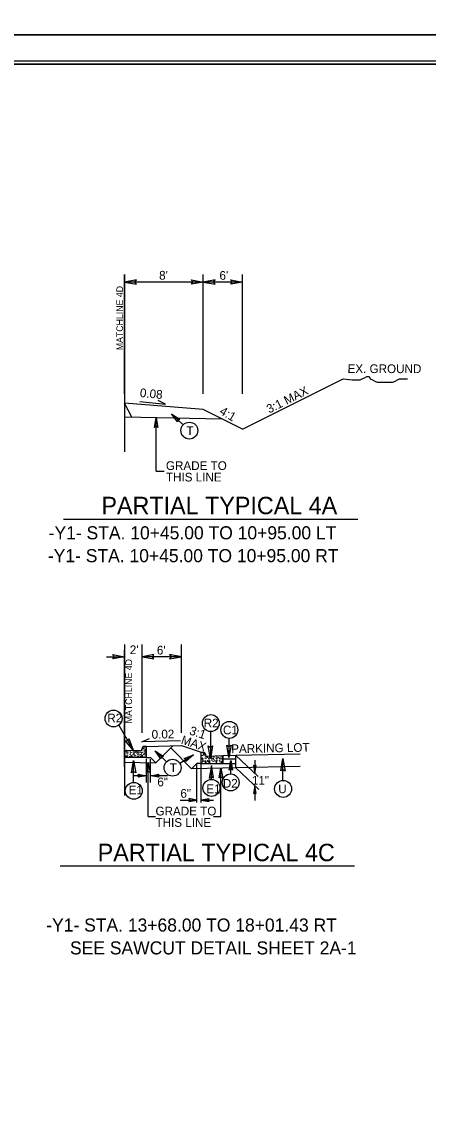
# Model space of a CAD drawing. Extents: x 2320980 to 2456309, y 595047 to 606177.
# Drawn here: x 2455879.6 to 2455941.7, y 596577.9 to 596743.6 of the extents above; entities that cross this region are included whole.
import ezdxf

# ---------------------------------------------------------------- set-up
doc = ezdxf.new("R2010")
doc.units = 0
for name, color, linetype in [('Matchline', 7, 'Continuous'), ('Matchline Text', 7, 'Continuous'), ('Old_Level_1', 7, 'Continuous'), ('Old_Level_2', 7, 'Continuous'), ('Old_Level_20', 7, 'Continuous'), ('Old_Level_21', 7, 'Continuous'), ('Old_Level_3', 7, 'Continuous'), ('Prop Dimension', 7, 'Continuous'), ('Prop Dimension Text', 7, 'Continuous'), ('Prop Terminator CELL', 7, 'Continuous'), ('Sheet Plan CELL', 7, 'Continuous'), ('Sheet Plot Border Inside CELL', 7, 'Continuous'), ('Sheet Plot Border Outside CELL', 7, 'Continuous'), ('Typical Berm CELL', 7, 'Continuous'), ('Typical Curb CELL', 7, 'Continuous'), ('Typical ID Circle CELL', 7, 'Continuous'), ('Typical Pavement Slope CELL', 7, 'Continuous'), ('Typical Pavement Slope Information CELL', 7, 'Continuous'), ('Typical Slope Point Local CELL', 7, 'Continuous'), ('Typical Terminator CELL', 7, 'Continuous')]:
    doc.layers.add(name, color=color, linetype=linetype)

msp = doc.modelspace()

# ---------------------------------------------------------------- linework, layer by layer
at = {"layer": 'Matchline'}
for p, q in [((2455895.35, 596705.01), (2455895.35, 596677.92)), ((2455895.35, 596648.55), (2455895.35, 596625.48))]:
    msp.add_line(p, q, dxfattribs=at)
at = {"layer": 'Old_Level_1'}
for p, q in [((2455922.11, 596631.78), (2455912.33, 596631.58)), ((2455922.11, 596629.91), (2455912.33, 596629.7))]:
    msp.add_line(p, q, dxfattribs=at)
at = {"layer": 'Old_Level_21'}
for p, q in [((2455895.35, 596686.78), (2455895.35, 596705.01)), ((2455907.35, 596703.85), (2455895.35, 596703.85)), ((2455907.35, 596686.78), (2455907.35, 596705.01)), ((2455913.35, 596703.85), (2455907.35, 596703.85)), ((2455913.35, 596686.78), (2455913.35, 596705.01)), ((2455900.15, 596674.97), (2455901.39, 596674.97)), ((2455895.35, 596629.88), (2455895.35, 596647.68)), ((2455898.01, 596635.07), (2455898.01, 596648.55)), ((2455904.01, 596635.07), (2455904.01, 596648.55)), ((2455892.6, 596646.67), (2455895.35, 596646.67)), ((2455904.01, 596646.67), (2455898.01, 596646.67)), ((2455898.67, 596627.49), (2455898.67, 596631.08)), ((2455899.3, 596627.49), (2455899.3, 596631.04)), ((2455906.37, 596624.42), (2455906.37, 596630.37)), ((2455907.01, 596624.42), (2455907.01, 596630.37)), ((2455898.96, 596622.29), (2455900.08, 596622.29)), ((2455908.91, 596622.29), (2455910.05, 596622.29))]:
    msp.add_line(p, q, dxfattribs=at)
at = {"layer": 'Old_Level_3'}
for p, q in [((2455886, 596667.68), (2455930.92, 596667.68)), ((2455885.51, 596614.73), (2455930.43, 596614.73))]:
    msp.add_line(p, q, dxfattribs=at)
at = {"layer": 'Prop Dimension'}
for p, q in [((2455912.33, 596631.58), (2455915.71, 596628.39)), ((2455915.21, 596630.86), (2455915.21, 596628.86)), ((2455912.33, 596629.7), (2455915.83, 596626.4)), ((2455915.21, 596626.99), (2455915.21, 596624.74))]:
    msp.add_line(p, q, dxfattribs=at)
at = {"layer": 'Prop Dimension Text'}
for p, q in [((2455904.28, 596682.06), (2455902.52, 596683.74)), ((2455900.15, 596674.97), (2455900.15, 596683.16)), ((2455901.74, 596630.63), (2455899.99, 596632.31)), ((2455903.77, 596630.41), (2455905.84, 596631.7)), ((2455911.53, 596628.77), (2455911.53, 596630.85)), ((2455898.96, 596622.29), (2455898.96, 596630.48)), ((2455910.05, 596622.29), (2455910.05, 596629.66)), ((2455898.67, 596628.5), (2455896.78, 596628.5)), ((2455901.87, 596628.5), (2455899.3, 596628.5)), ((2455903.81, 596624.78), (2455906.37, 596624.78)), ((2455907.01, 596624.78), (2455908.89, 596624.78))]:
    msp.add_line(p, q, dxfattribs=at)
for points in [[(2455897.67, 596685.6), (2455901.57, 596685.23), (2455900.46, 596685.79)], [(2455903.85, 596633.85), (2455897.99, 596633.69), (2455899.13, 596634.18)]]:
    msp.add_lwpolyline(points, dxfattribs=at)
for centre in [(2455905.22, 596681.17), (2455893.66, 596637.24), (2455908.5, 596636.54), (2455911.33, 596635.49), (2455902.67, 596629.73), (2455896.74, 596626.2), (2455908.59, 596626.64), (2455911.53, 596627.48), (2455919.53, 596626.49)]:
    msp.add_circle(centre, 1.29, dxfattribs=at)
at = {"layer": 'Prop Terminator CELL'}
for points in [[(2455915, 596630.06), (2455915.21, 596628.86), (2455915.42, 596630.07), (2455915.21, 596629.91)], [(2455915.41, 596625.79), (2455915.21, 596626.99), (2455914.99, 596625.78), (2455915.21, 596625.94)]]:
    msp.add_lwpolyline(points, close=True, dxfattribs=at)
at = {"layer": 'Sheet Plan CELL'}
for points in [[(2456042.11, 596737.08), (2455742.1, 596737.08), (2455742.1, 596527.08), (2456042.11, 596527.08)], [(2455742.1, 596527.08), (2455742.1, 596737.07), (2456002.1, 596737.08), (2456002.1, 596707.07), (2456042.11, 596707.06), (2456042.11, 596527.08)]]:
    msp.add_lwpolyline(points, close=True, dxfattribs=at)
at = {"layer": 'Sheet Plot Border Inside CELL'}
msp.add_lwpolyline([(2455711.41, 596526.57), (2456044.6, 596526.58), (2456044.61, 596737.57), (2455711.41, 596737.57)], close=True, dxfattribs=at)
at = {"layer": 'Sheet Plot Border Outside CELL'}
for points in [[(2455708.81, 596741.57), (2456045.51, 596741.57), (2456045.51, 596960.57), (2455708.81, 596960.57)], [(2455708.81, 596522.57), (2456045.51, 596522.57), (2456045.51, 596741.57), (2455708.81, 596741.57)]]:
    msp.add_lwpolyline(points, close=True, dxfattribs=at)
at = {"layer": 'Typical Berm CELL'}
for p, q in [((2455898.67, 596632.98), (2455904.01, 596633.09)), ((2455904.01, 596633.09), (2455907.01, 596632.09)), ((2455898.67, 596631.26), (2455899.29, 596631.26)), ((2455907.01, 596630.37), (2455906.38, 596630.37))]:
    msp.add_line(p, q, dxfattribs=at)
at = {"layer": 'Typical Curb CELL'}
for p, q in [((2455895.35, 596632.42), (2455897.67, 596632.33)), ((2455898.01, 596632.64), (2455898.01, 596632.66)), ((2455898.12, 596632.62), (2455898.2, 596632.78)), ((2455898.34, 596632.68), (2455898.12, 596632.62)), ((2455898.2, 596632.78), (2455898.34, 596632.68)), ((2455898.67, 596632.98), (2455898.32, 596632.98)), ((2455898.42, 596632.53), (2455898.44, 596632.41)), ((2455898.62, 596632.47), (2455898.42, 596632.53)), ((2455898.44, 596632.41), (2455898.62, 596632.47)), ((2455898.67, 596631.26), (2455898.67, 596632.98)), ((2455898.67, 596631.26), (2455895.35, 596631.26)), ((2455895.48, 596631.36), (2455895.6, 596631.52)), ((2455895.64, 596631.37), (2455895.48, 596631.36)), ((2455895.6, 596631.52), (2455895.64, 596631.37)), ((2455895.69, 596631.97), (2455895.81, 596632.12)), ((2455895.85, 596631.97), (2455895.69, 596631.97)), ((2455895.81, 596632.12), (2455895.85, 596631.97)), ((2455896.27, 596631.46), (2455896.39, 596631.62)), ((2455896.43, 596631.46), (2455896.27, 596631.46)), ((2455896.39, 596631.62), (2455896.43, 596631.46)), ((2455896.71, 596631.9), (2455896.79, 596632.05)), ((2455896.93, 596631.95), (2455896.71, 596631.9)), ((2455896.79, 596632.05), (2455896.93, 596631.95)), ((2455897.29, 596631.39), (2455897.37, 596631.54)), ((2455897.51, 596631.44), (2455897.29, 596631.39)), ((2455897.36, 596631.97), (2455897.47, 596632.12)), ((2455897.51, 596631.97), (2455897.36, 596631.97)), ((2455897.37, 596631.54), (2455897.51, 596631.44)), ((2455897.47, 596632.12), (2455897.51, 596631.97)), ((2455897.93, 596631.46), (2455898.05, 596631.62)), ((2455898.09, 596631.46), (2455897.93, 596631.46)), ((2455898.05, 596631.62), (2455898.09, 596631.46)), ((2455898.37, 596631.9), (2455898.45, 596632.05)), ((2455898.59, 596631.95), (2455898.37, 596631.9)), ((2455898.45, 596632.05), (2455898.59, 596631.95)), ((2455907.01, 596630.37), (2455907.01, 596632.09)), ((2455907.01, 596632.09), (2455907.35, 596632.09)), ((2455907.06, 596631.58), (2455907.26, 596631.64)), ((2455907.24, 596631.52), (2455907.06, 596631.58)), ((2455907.22, 596631.16), (2455907.09, 596631.06)), ((2455907.09, 596631.06), (2455907.31, 596631.01)), ((2455907.31, 596631.01), (2455907.22, 596631.16)), ((2455907.26, 596631.64), (2455907.24, 596631.52)), ((2455907.47, 596631.89), (2455907.34, 596631.79)), ((2455907.34, 596631.79), (2455907.56, 596631.74)), ((2455907.56, 596631.74), (2455907.47, 596631.89)), ((2455907.63, 596630.73), (2455907.59, 596630.58)), ((2455907.59, 596630.58), (2455907.74, 596630.57)), ((2455907.74, 596630.57), (2455907.63, 596630.73)), ((2455907.67, 596631.75), (2455907.67, 596631.77)), ((2455910.33, 596631.53), (2455908, 596631.44)), ((2455908.21, 596631.24), (2455908.16, 596631.08)), ((2455908.16, 596631.08), (2455908.32, 596631.08)), ((2455908.31, 596630.65), (2455908.17, 596630.55)), ((2455908.17, 596630.55), (2455908.39, 596630.5)), ((2455908.32, 596631.08), (2455908.21, 596631.24)), ((2455908.39, 596630.5), (2455908.31, 596630.65)), ((2455908.88, 596631.16), (2455908.75, 596631.06)), ((2455908.75, 596631.06), (2455908.97, 596631.01)), ((2455908.97, 596631.01), (2455908.88, 596631.16)), ((2455909.29, 596630.73), (2455909.25, 596630.58)), ((2455909.25, 596630.58), (2455909.41, 596630.57)), ((2455909.41, 596630.57), (2455909.29, 596630.73)), ((2455909.87, 596631.24), (2455909.82, 596631.08)), ((2455909.82, 596631.08), (2455909.98, 596631.08)), ((2455909.98, 596631.08), (2455909.87, 596631.24)), ((2455910.08, 596630.63), (2455910.04, 596630.48)), ((2455910.2, 596630.48), (2455910.08, 596630.63)), ((2455910.33, 596630.37), (2455910.33, 596631.53)), ((2455912.33, 596629.7), (2455912.33, 596631.58)), ((2455907.01, 596630.37), (2455910.33, 596630.37)), ((2455910.04, 596630.48), (2455910.2, 596630.48))]:
    msp.add_line(p, q, dxfattribs=at)
for centre in [(2455895.39, 596632.22), (2455895.47, 596632.18), (2455895.61, 596632.34), (2455895.74, 596632.23), (2455895.8, 596632.37), (2455896, 596632.28), (2455896.27, 596632.26), (2455896.29, 596632.33), (2455896.63, 596632.29), (2455896.79, 596632.22), (2455897.05, 596632.22), (2455897.13, 596632.18), (2455897.27, 596632.29), (2455897.4, 596632.23), (2455897.66, 596632.28), (2455897.93, 596632.26), (2455897.95, 596632.33), (2455898.08, 596632.5), (2455898.24, 596632.44), (2455898.3, 596632.29), (2455898.36, 596632.88), (2455898.46, 596632.22), (2455898.58, 596632.59), (2455898.65, 596632.83), (2455895.36, 596631.68), (2455895.37, 596632.09), (2455895.44, 596631.9), (2455895.56, 596631.59), (2455895.57, 596631.97), (2455895.64, 596631.65), (2455895.8, 596631.67), (2455895.82, 596631.55), (2455895.85, 596631.75), (2455896.04, 596632.15), (2455896.13, 596631.72), (2455896.15, 596631.46), (2455896.23, 596632.03), (2455896.28, 596631.83), (2455896.35, 596631.68), (2455896.4, 596632.07), (2455896.59, 596631.76), (2455896.61, 596631.64), (2455896.81, 596631.52), (2455896.82, 596631.71), (2455896.86, 596631.32), (2455896.98, 596631.56), (2455897.02, 596631.68), (2455897.03, 596632.09), (2455897.11, 596631.9), (2455897.23, 596631.97), (2455897.3, 596631.65), (2455897.37, 596631.71), (2455897.51, 596631.75), (2455897.61, 596631.59), (2455897.63, 596631.71), (2455897.68, 596631.4), (2455897.7, 596632.15), (2455897.7, 596631.67), (2455897.79, 596631.72), (2455897.81, 596631.46), (2455897.89, 596632.03), (2455897.94, 596631.83), (2455898.02, 596631.68), (2455898.06, 596632.07), (2455898.25, 596631.76), (2455898.27, 596631.64), (2455898.47, 596631.52), (2455898.48, 596631.71), (2455898.52, 596631.32), (2455898.64, 596631.56), (2455907.02, 596631.94), (2455907.04, 596630.67), (2455907.09, 596631.7), (2455907.2, 596630.82), (2455907.21, 596630.64), (2455907.22, 596631.33), (2455907.31, 596631.99), (2455907.38, 596631.4), (2455907.4, 596630.75), (2455907.43, 596630.87), (2455907.44, 596631.55), (2455907.6, 596631.61), (2455907.62, 596631.18), (2455907.66, 596630.79), (2455907.72, 596631.44), (2455907.74, 596630.94), (2455907.75, 596631.37), (2455907.78, 596631.15), (2455907.87, 596630.57), (2455907.89, 596630.83), (2455907.97, 596630.78), (2455907.98, 596631.26), (2455907.99, 596630.51), (2455908.02, 596631.39), (2455908.05, 596630.83), (2455908.07, 596630.7), (2455908.16, 596630.86), (2455908.28, 596631.34), (2455908.31, 596630.83), (2455908.38, 596630.77), (2455908.41, 596631.4), (2455908.44, 596631.08), (2455908.55, 596631.29), (2455908.57, 596631.02), (2455908.63, 596631.33), (2455908.65, 596631.21), (2455908.66, 596630.8), (2455908.7, 596630.67), (2455908.86, 596630.82), (2455908.87, 596630.64), (2455908.88, 596631.33), (2455909.04, 596631.4), (2455909.06, 596630.75), (2455909.09, 596630.87), (2455909.28, 596631.18), (2455909.32, 596630.79), (2455909.38, 596631.44), (2455909.4, 596630.94), (2455909.41, 596631.37), (2455909.44, 596631.15), (2455909.53, 596630.57), (2455909.55, 596630.83), (2455909.64, 596631.26), (2455909.68, 596631.39), (2455909.82, 596630.86), (2455909.85, 596630.66), (2455909.88, 596631.48), (2455909.88, 596630.78), (2455909.94, 596631.34), (2455910.04, 596630.77), (2455910.07, 596631.46), (2455910.11, 596631.08), (2455910.11, 596630.7), (2455910.21, 596631.29), (2455910.23, 596631.02), (2455910.29, 596631.33), (2455910.31, 596631.21), (2455910.32, 596630.8), (2455907.16, 596630.43), (2455908.82, 596630.43)]:
    msp.add_circle(centre, 0.0107, dxfattribs=at)
for centre, start, end in [((2455897.69, 596632.64), 267.6155, 360), ((2455898.32, 596632.66), 90, 180), ((2455907.35, 596631.77), 0, 90), ((2455907.99, 596631.75), 180, 272.3845)]:
    msp.add_arc(centre, 0.319, start, end, dxfattribs=at)
at = {"layer": 'Typical ID Circle CELL'}
for p, q in [((2455894.44, 596636.21), (2455896.66, 596632.39)), ((2455908.45, 596635.27), (2455908.45, 596631.14)), ((2455911.27, 596634.22), (2455911.27, 596631.28)), ((2455896.71, 596627.5), (2455896.71, 596630.84)), ((2455919.5, 596627.79), (2455919.5, 596631.13)), ((2455908.61, 596627.94), (2455908.6, 596630.02))]:
    msp.add_line(p, q, dxfattribs=at)
at = {"layer": 'Typical Pavement Slope CELL'}
for p, q in [((2455907.35, 596684.41), (2455895.35, 596685.38)), ((2455896.46, 596683.23), (2455895.35, 596685.38)), ((2455895.35, 596683.25), (2455910.25, 596682.96)), ((2455902.71, 596633.06), (2455900.1, 596630.45)), ((2455905.57, 596629.56), (2455902.39, 596632.74)), ((2455895.35, 596630.55), (2455900.1, 596630.45)), ((2455899.29, 596631.26), (2455900.1, 596630.45)), ((2455912.33, 596631.58), (2455910.33, 596631.53)), ((2455912.33, 596631.58), (2455910.33, 596631.53)), ((2455910.33, 596631.53), (2455910.33, 596631.03)), ((2455912.33, 596631.07), (2455910.33, 596631.03)), ((2455910.33, 596631.03), (2455912.33, 596631.07)), ((2455911.33, 596631.05), (2455910.33, 596631.03)), ((2455910.33, 596631.03), (2455910.33, 596630.37)), ((2455912.33, 596631.07), (2455911.33, 596631.05)), ((2455912.33, 596631.07), (2455912.33, 596631.58)), ((2455912.33, 596630.37), (2455912.33, 596631.07)), ((2455906.38, 596630.37), (2455905.57, 596629.56)), ((2455910.33, 596629.66), (2455905.58, 596629.57)), ((2455910.33, 596630.37), (2455912.33, 596630.37)), ((2455910.33, 596630.37), (2455912.33, 596630.37)), ((2455912.33, 596629.7), (2455910.33, 596629.66))]:
    msp.add_line(p, q, dxfattribs=at)
at = {"layer": 'Typical Slope Point Local CELL'}
for q in [(2455928.68, 596689.08), (2455907.35, 596684.41)]:
    msp.add_line((2455913.35, 596681.41), q, dxfattribs=at)
msp.add_lwpolyline([(2455928.68, 596689.08), (2455930.06, 596688.91), (2455930.41, 596688.91), (2455930.92, 596688.91), (2455931.27, 596688.91), (2455931.61, 596689.08), (2455931.96, 596689.25), (2455932.3, 596689.42), (2455932.65, 596689.42), (2455932.82, 596689.08), (2455933.17, 596688.91), (2455933.51, 596688.73), (2455933.86, 596688.56), (2455934.2, 596688.56), (2455934.55, 596688.56), (2455934.89, 596688.56), (2455935.24, 596688.56), (2455935.58, 596688.56), (2455935.93, 596688.56), (2455936.27, 596688.56), (2455936.62, 596688.73), (2455936.96, 596688.91), (2455937.31, 596689.08), (2455937.82, 596689.08), (2455938.17, 596689.08), (2455938.51, 596689.08)], dxfattribs=at)
at = {"layer": 'Typical Terminator CELL'}
for points in [[(2455897.14, 596704.16), (2455895.35, 596703.85), (2455897.15, 596703.54), (2455896.92, 596703.85)], [(2455905.55, 596704.16), (2455907.35, 596703.85), (2455905.54, 596703.54), (2455905.77, 596703.85)], [(2455909.14, 596704.16), (2455907.35, 596703.85), (2455909.15, 596703.54), (2455908.92, 596703.85)], [(2455911.55, 596704.16), (2455913.35, 596703.85), (2455911.54, 596703.54), (2455911.77, 596703.85)], [(2455903.43, 596682.52), (2455902.52, 596683.74), (2455903.79, 596682.89), (2455903.47, 596682.83)], [(2455899.9, 596681.66), (2455900.15, 596683.16), (2455900.42, 596681.65), (2455900.15, 596681.85)], [(2455893.55, 596646.98), (2455895.35, 596646.67), (2455893.54, 596646.35), (2455893.77, 596646.67)], [(2455899.8, 596646.98), (2455898.01, 596646.67), (2455899.81, 596646.35), (2455899.58, 596646.67)], [(2455902.21, 596646.36), (2455904.01, 596646.67), (2455902.2, 596646.99), (2455902.43, 596646.67)], [(2455895.99, 596634.19), (2455896.66, 596632.39), (2455895.41, 596633.87), (2455895.82, 596633.83)], [(2455900.89, 596631.09), (2455899.99, 596632.31), (2455901.26, 596631.46), (2455900.93, 596631.4)], [(2455908.78, 596633.04), (2455908.45, 596631.14), (2455908.11, 596633.05), (2455908.45, 596632.8)], [(2455911.6, 596633.17), (2455911.27, 596631.28), (2455910.94, 596633.18), (2455911.27, 596632.94)], [(2455896.39, 596628.94), (2455896.71, 596630.84), (2455897.05, 596628.93), (2455896.71, 596629.17)], [(2455904.43, 596631.13), (2455905.84, 596631.7), (2455904.7, 596630.68), (2455904.72, 596631)], [(2455911.28, 596629.36), (2455911.53, 596630.85), (2455911.8, 596629.35), (2455911.53, 596629.54)], [(2455919.18, 596629.23), (2455919.5, 596631.13), (2455919.84, 596629.22), (2455919.5, 596629.47)], [(2455898.7, 596628.98), (2455898.96, 596630.48), (2455899.22, 596628.97), (2455898.96, 596629.16)], [(2455908.93, 596628.16), (2455908.59, 596630.05), (2455908.27, 596628.15), (2455908.6, 596628.39)], [(2455909.79, 596628.16), (2455910.05, 596629.66), (2455910.31, 596628.15), (2455910.05, 596628.34)], [(2455897.42, 596628.72), (2455898.67, 596628.5), (2455897.42, 596628.28), (2455897.58, 596628.5)], [(2455900.55, 596628.29), (2455899.3, 596628.5), (2455900.56, 596628.73), (2455900.4, 596628.5)], [(2455905.13, 596624.57), (2455906.37, 596624.78), (2455905.12, 596625.01), (2455905.28, 596624.78)], [(2455908.25, 596625), (2455907.01, 596624.78), (2455908.26, 596624.56), (2455908.1, 596624.78)]]:
    msp.add_lwpolyline(points, close=True, dxfattribs=at)

# ---------------------------------------------------------------- texts
at = {"layer": 'Matchline Text'}
for p in [(2455895.09, 596693.44), (2455896.47, 596636.5)]:
    msp.add_text('MATCHLINE 4D', height=1, rotation=90, dxfattribs=at).set_placement(p)
at = {"layer": 'Old_Level_1'}
msp.add_text('EX. GROUND', height=1.33, rotation=359.9103, dxfattribs=at).set_placement((2455929.36, 596689.96))
at = {"layer": 'Old_Level_2'}
for s, height, p in [('PARTIAL TYPICAL 4A', 2.66, (2455891.81, 596668.41)), ('-Y1- STA. 10+45.00 TO 10+95.00 LT', 1.995, (2455883.76, 596664.58)), ('-Y1- STA. 10+45.00 TO 10+95.00 RT', 1.995, (2455883.64, 596661.09)), ('PARTIAL TYPICAL 4C', 2.66, (2455891.24, 596615.46)), ('-Y1- STA. 13+68.00 TO 18+01.43 RT', 1.995, (2455883.39, 596604.72)), ('SEE SAWCUT DETAIL SHEET 2A-1', 1.995, (2455887.01, 596601.23))]:
    msp.add_text(s, height=height, dxfattribs=at).set_placement(p)
at = {"layer": 'Old_Level_20'}
for s, p in [('T', (2455904.78, 596680.5)), ('R2', (2455892.71, 596636.64)), ('R2', (2455907.42, 596635.88)), ('C1', (2455910.35, 596634.82)), ('T', (2455902.24, 596629.07)), ('E1', (2455895.95, 596625.67)), ('E1', (2455907.81, 596625.84)), ('U', (2455918.79, 596625.83))]:
    msp.add_text(s, height=1.33, dxfattribs=at).set_placement(p)
msp.add_text('D2', height=1.33, rotation=359.9972, dxfattribs=at).set_placement((2455910.33, 596626.68))
at = {"layer": 'Old_Level_21'}
for s, p in [("8'", (2455900.61, 596704.21)), ("6'", (2455909.82, 596704.19)), ('GRADE TO', (2455901.65, 596675.16)), ('THIS LINE', (2455901.65, 596673.41)), ("6'", (2455900.27, 596647)), ('6"', (2455900.34, 596626.89)), ('6"', (2455903.86, 596625.14)), ('GRADE TO', (2455900.06, 596622.44)), ('THIS LINE', (2455900.06, 596620.7))]:
    msp.add_text(s, height=1.33, dxfattribs=at).set_placement(p)
for s, rotation, p in [('0.08', 354.6583, (2455897.63, 596686.31)), ('3:1 MAX', 26.5659, (2455917.41, 596683.77)), ('4:1', 329.3616, (2455909.71, 596683.79)), ("2'", 0.0002, (2455896.14, 596647.06)), ('0.02', 1.1456, (2455899.48, 596634.15)), ('3:1', 341.5651, (2455905.13, 596634.84)), ('MAX', 341.5651, (2455903.86, 596633.43)), ('PARKING LOT', 1.1456, (2455911.62, 596631.94))]:
    msp.add_text(s, height=1.33, rotation=rotation, dxfattribs=at).set_placement(p)
at = {"layer": 'Typical Pavement Slope Information CELL'}
msp.add_text('11"', height=1.33, dxfattribs=at).set_placement((2455914.77, 596627.13))

doc.saveas('drawing.dxf')
